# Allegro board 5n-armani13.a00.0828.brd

Outline 226.83 x 115.8 mm; copper layers: TOP, GND1, IN1, VCC, IN2, IN3, GND2, BOTTOM. Coordinates in mm from the lower left corner of the outline.
Outline path: 0,101.3 arc(0.15,101.65) 0.5,101.8 2.2,101.8 arc(2.55,101.65) 2.7,101.3 2.7,101.24 2.7,101.23 arc(2.86,100.89) 3.2,100.75 6.98,100.75 arc(7.69,100.46) 7.98,99.75 7.98,97.48 arc(8.72,95.72) 10.48,95 14.44,95 arc(15.59,95.23) 16.56,95.88 17.1,96.42 arc(18.08,97.07) 19.22,97.3 22.83,97.3 arc(25.65,98.46) 26.83,101.27 26.83,108.59 arc(26.91,108.97) 27.12,109.29 29.54,111.71 arc(29.86,111.92) 30.25,112 79.83,112 arc(80.18,112.14) 80.33,112.48 80.33,112.49 80.33,113 arc(80.48,113.35) 80.83,113.5 91.83,113.5 arc(92.53,113.78) 92.83,114.48 92.83,114.49 92.83,114.8 arc(93.12,115.51) 93.83,115.8 155.38,115.8 arc(156.09,115.51) 156.38,114.8 156.38,112.32 arc(158.88,109.85) 161.38,112.32 161.38,114.8 arc(161.67,115.51) 162.38,115.8 195.84,115.8 arc(196.52,115.53) 196.84,114.88 arc(198.33,113.5) 199.83,114.88 arc(200.15,115.53) 200.82,115.8 209.52,115.8 arc(210.23,115.51) 210.52,114.8 210.52,98.35 arc(210.23,97.64) 209.52,97.35 208.78,97.35 arc(206.63,95.2) 208.78,93.05 210.72,93.05 arc(211.43,92.76) 211.72,92.05 211.72,58.89 arc(211.55,58.32) 211.08,57.96 210.04,57.55 210.02,57.54 arc(208.84,54.74) 211.64,53.56 arc(212.43,53.53) 212.95,52.94 212.96,52.91 arc(216.06,46.06) 220.55,40.03 220.58,39.99 arc(220.77,39.69) 220.83,39.33 220.83,25.22 220.83,25.21 arc(221.13,24.51) 221.83,24.23 225.83,24.23 arc(226.54,23.94) 226.83,23.23 226.83,1 arc(226.54,0.29) 225.83,0 214.07,0 arc(213.36,0.29) 213.07,1 213.07,4.28 213.07,4.44 arc(213.07,4.44) 213.07,4.44 213.07,4.46 arc(210.9,8.59) 206.28,9.13 206.22,9.11 arc(204.48,8.63) 202.68,8.47 152.95,8.47 arc(152.5,8.36) 152.15,8.07 arc(151.79,7.77) 151.35,7.67 112.49,7.67 arc(111.37,7.77) 110.29,8.08 110.29,8.08 arc(109.6,8.28) 108.88,8.35 106.53,8.35 arc(105.13,7.77) 104.53,6.38 104.53,6.36 104.53,3 arc(104.24,2.29) 103.53,2 25.02,2 arc(19.55,3.32) 15.28,6.99 15.27,7 arc(13.85,8.21) 12.03,8.65 4.76,8.65 arc(3.35,9.24) 2.76,10.65 2.76,43.85 5.53,43.85 5.53,43.29 5.53,43.28 arc(5.98,42.85) 6.43,43.28 6.43,43.29 6.43,43.85 11.28,43.85 11.28,43.83 arc(12.14,43.51) 11.78,44.35 11.78,50.45 arc(12.14,51.29) 11.28,50.97 11.28,50.95 8.03,50.95 8.03,51.51 8.03,51.52 arc(7.58,51.95) 7.13,51.52 7.13,51.51 7.13,50.95 1.56,50.95 1.56,51.61 1.56,51.62 arc(1.39,52.16) 0.95,52.52 0.9,52.54 arc(0.47,52.91) 0.31,53.46 0.31,55 arc(0.58,55.69) 1.26,56 arc(1.92,56.3) 2.2,56.98 2.2,56.99 2.2,58.65 9.18,58.65 arc(9.68,59.15) 9.18,59.65 9.18,73.15 arc(9.68,73.65) 9.18,74.15 2.2,74.15 2.2,76.71 2.2,76.73 arc(2.01,77.3) 1.52,77.65 arc(1.02,78.01) 0.83,78.6 0.83,79.7 0.83,79.7 arc(0.03,81.18) 1.33,82.25 1.42,82.25 4.56,82.25 4.56,82.23 arc(5.42,81.91) 5.06,82.75 5.06,91.25 arc(5.42,92.1) 4.56,91.77 4.56,91.75 0,91.75 0,94.64 2.16,94.64 arc(2.84,94.91) 3.15,95.58 3.16,95.6 3.16,95.6 3.16,95.62 arc(2.86,96.32) 2.16,96.6 0,96.6 0,101.3

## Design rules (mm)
net group 45-50OHM(5|4.8|5.5|4.8): nets CSA0_1# CSA1_1#
net group (5/5): nets PROCHOT#_R VR_HOT#_VCPU
net group (15/15): nets I2C0_SCL_TCH_PAD I2C_SCL_TP_MOS
net group (20): nets AUX EDP_COMP
net group (20/20): nets M_CHA_VREF_CA M_CHB_VREF_CA
net group (40): nets RING2 SLEEVE
net group (GND_20): nets AGND GND
net group AU1_CBN: nets AU1_CBN AU1_CBP
net group AUX_ON: nets AUX_ON PU5102_EN2_A
net group AZ_BITCLK_1: nets AZ_BITCLK_1 HDA_BCLK_R
net group AZ_SDATA_IN0: nets AZ_SDATA_IN0 SDATA_IN_R
net group AZ_SDATA_OUT_1: nets AZ_SDATA_OUT_1 HDA_SDO_R
net group AZ_SYNC_1: nets AZ_SYNC_1 HDA_SYNC_R
net group CCG4_I2C_SCL: nets CCG4_I2C_SCL TYPEC_SMBCLK
net group CCG4_I2C_SDA: nets CCG4_I2C_SDA TYPEC_SMBDA
net group CFAN_PWM_R: nets CFAN_PWM_R FAN1_PWM
net group CHG_BGATE_C: nets CHG_BGATE_C CHG_BGATE_R_C
net group CHG_CSON: nets CHG_CSON CHG_CSOP
net group CHG_DCIN_B: nets CHG_DCIN_B CHG_DCIN_R
net group CHG_PROCHOT#: nets CHG_PROCHOT# PROCHOT#
net group CHG_PSYS: nets CHG_PSYS CHG_PSYS_R
net group CHG_SCL_R: nets CHG_SCL_R CHG_SMBCLK
net group CHG_SDA_R: nets CHG_SDA_R CHG_SMBDAT
net group CHG_UG1_D: nets CHG_UG1_D CHG_UG1_R_D
net group CHG_UG2_D: nets CHG_UG2_D CHG_UG2_R_D
net group CLK_PCIE_SSD_REQ#_R: nets CLK_PCIE_NVME_REQ# CLK_PCIE_SSD_REQ#_R
net group CMP_VOUT0: nets CMP_VOUT0 N148505031
net group COMP_B_VCPU: nets COMP_B_VCPU COMP_B_VCPU_R
net group CPU_DP1_HPD: nets CPU_DP1_HPD HDMI_HPD
net group CTAL_1: nets CTAL_1 RTC_X1
net group DC_IN_OK: nets DC_IN_OK HW_ACAVIN_NB
net group DDPC_AUXN: nets DDPC_AUXN OUT1_DP_AUXN_C
net group DDPC_AUXP: nets DDPC_AUXP OUT1_DP_AUXP_C
net group DEVSLP0_HDD: nets DEVSLP0_HDD HDD_DEVSLP
net group DEVSLP2_SSD: nets DEVSLP2_SSD SSD_DEVSLP
net group DMIC_CLK: nets DMIC_CLK DMIC_CLK_R
net group DMIC_DATA: nets DMIC_DATA DMIC_DATA_R
net group DN1: nets DN1 DN1_MUX
net group DN2: nets DN2 DN2_MUX
net group DP1: nets DP1 DP1_MUX
net group DP2: nets DP2 DP2_MUX
net group DP_DDI2_DATA0: nets DP_DDI2_DATA0 OUT1_DP_D0P_C
net group DP_DDI2_DATA0#: nets DP_DDI2_DATA0# OUT1_DP_D0N_C
net group DP_DDI2_DATA1: nets DP_DDI2_DATA1 OUT1_DP_D1P_C
net group DP_DDI2_DATA1#: nets DP_DDI2_DATA1# OUT1_DP_D1N_C
net group DP_DDI2_DATA2: nets DP_DDI2_DATA2 OUT1_DP_D2P_C
net group DP_DDI2_DATA2#: nets DP_DDI2_DATA2# OUT1_DP_D2N_C
net group DP_DDI2_DATA3: nets DP_DDI2_DATA3 OUT1_DP_D3P_C
net group DP_DDI2_DATA3#: nets DP_DDI2_DATA3# OUT1_DP_D3N_C
net group EC_MUTE#: nets EC_MUTE# NB_MUTE#
net group EDP_AUXN: nets EDP_AUXN EDP_AUXN_CC
net group EDP_AUXP: nets EDP_AUXP EDP_AUXP_CC
net group EDP_HPD: nets EDP_HPD EDP_HPD_R
net group EDP_TXN0: nets EDP_TXN0 EDP_TXN0_CC
net group EDP_TXN1: nets EDP_TXN1 EDP_TXN1_CC
net group EDP_TXP0: nets EDP_TXP0 EDP_TXP0_CC
net group EDP_TXP1: nets EDP_TXP1 EDP_TXP1_CC
net group EMMC_CCLK: nets EMMC_CCLK EMMC_CLK_R
net group ESPI_CLK: nets ESPI_CLK PCH_ESPI_CLK
net group ESPI_CS#: nets ESPI_CS# PCH_ESPI_CS#
net group ESPI_IO0: nets ESPI_IO0 PCH_ESPI_IO0
net group ESPI_IO1: nets ESPI_IO1 PCH_ESPI_IO1
net group ESPI_IO2: nets ESPI_IO2 PCH_ESPI_IO2
net group ESPI_IO3: nets ESPI_IO3 PCH_ESPI_IO3
net group FFS_INT1: nets FFS_INT1 INT1
net group GPIO: nets GPU_OVERT GPU_PWR_LEVEL
net group GPU_OVERT_R: nets GPU_OVERT_R N148505032
net group GPU_THM_SMBCLK: nets GPU_THM_SMBCLK SML1_SMBCLK
net group GPU_THM_SMBDAT: nets GPU_THM_SMBDAT SML1_SMBDATA
net group H_CPU_SVIDALERT#: nets VIDALERT# VIDALERT#_VCPU
net group H_CPU_SVIDCLK: nets H_CPU_SVIDCLK VIDSCLK
net group H_PECI: nets H_PECI PECI_PCH
net group HDMI_DDC: nets N153451943 N153451944
net group HPOUT_L: nets HPOUT_L RR_HPOUT_L
net group HPOUT_R: nets HPOUT_R RR_HPOUT_R
net group L_BKLT_CTRL: nets L_BKLT_CTRL L_BKLT_CTRL_R
net group LANWAKE#: nets LAN_WAKE# LANWAKE#
net group M_CH_DRAM_RESET#: nets M_CH_DRAM_RESET# M_CH_DRAM_RESET#_R
net group M_OTHER: nets N16941314 N144273293
net group ME_SUS_PWR_ACK: nets ME_SUS_PWR_ACK SUSACK#
net group N147968560: nets N147968560 N147968575
net group PANEL_BKEN_EC: nets PANEL_BKEN_EC PANEL_BKEN_EC_R
net group PBAT_PRES#: nets N154222504 PBAT_PRES#
net group PCIE1_GPU_RXN: nets PCIE1_GPU_RXN PCIE1_GPU_RXN_C
net group PCIE1_GPU_RXP: nets PCIE1_GPU_RXP PCIE1_GPU_RXP_C
net group PCIE1_GPU_TXN: nets PCIE1_GPU_TXN PCIE1_GPU_TXN_C
net group PCIE1_GPU_TXP: nets PCIE1_GPU_TXP PCIE1_GPU_TXP_C
net group PCIE2_GPU_RXN: nets PCIE2_GPU_RXN PCIE2_GPU_RXN_C
net group PCIE2_GPU_RXP: nets PCIE2_GPU_RXP PCIE2_GPU_RXP_C
net group PCIE2_GPU_TXN: nets PCIE2_GPU_TXN PCIE2_GPU_TXN_C
net group PCIE2_GPU_TXP: nets PCIE2_GPU_TXP PCIE2_GPU_TXP_C
net group PCIE3_GPU_RXN: nets PCIE3_GPU_RXN PCIE3_GPU_RXN_C
net group PCIE3_GPU_RXP: nets PCIE3_GPU_RXP PCIE3_GPU_RXP_C
net group PCIE3_GPU_TXN: nets PCIE3_GPU_TXN PCIE3_GPU_TXN_C
net group PCIE3_GPU_TXP: nets PCIE3_GPU_TXP PCIE3_GPU_TXP_C
net group PCIE4_GPU_RXN: nets PCIE4_GPU_RXN PCIE4_GPU_RXN_C
net group PCIE4_GPU_RXP: nets PCIE4_GPU_RXP PCIE4_GPU_RXP_C
net group PCIE4_GPU_TXN: nets PCIE4_GPU_TXN PCIE4_GPU_TXN_C
net group PCIE4_GPU_TXP: nets PCIE4_GPU_TXP PCIE4_GPU_TXP_C
net group PCIE5_LAN_TXN: nets PCIE5_LAN_TXN PCIE5_LAN_TXN_C
net group PCIE5_LAN_TXP: nets PCIE5_LAN_TXP PCIE5_LAN_TXP_C
net group PCIE6_WLAN_TXN: nets PCIE6_WLAN_TXN PCIE6_WLAN_TXN_C
net group PCIE6_WLAN_TXP: nets PCIE6_WLAN_TXP PCIE6_WLAN_TXP_C
net group PCIE9_SSD1_TXN: nets PCIE9_SSD1_TXN PCIE9_SSD1_TXN_C
net group PCIE9_SSD1_TXP: nets PCIE9_SSD1_TXP PCIE9_SSD1_TXP_C
net group PCIE10_SSD1_TXN: nets PCIE10_SSD1_TXN PCIE10_SSD1_TXN_C
net group PCIE10_SSD1_TXP: nets PCIE10_SSD1_TXP PCIE10_SSD1_TXP_C
net group PCIE11_SSD1_TXN: nets PCIE11_SSD1_TXN PCIE11_SSD1_TXN_C
net group PCIE11_SSD1_TXP: nets PCIE11_SSD1_TXP PCIE11_SSD1_TXP_C
net group PCIE12_SATA_SSD1_RXN: nets PCIE12_SATA_SSD1_RXN PCIE12_SATA_SSD1_RXN_R
net group PCIE12_SATA_SSD1_RXP: nets PCIE12_SATA_SSD1_RXP PCIE12_SATA_SSD1_RXP_R
net group PCIE12_SATA_SSD1_TXN: nets PCIE12_SATA_SSD1_TXN PCIE12_SATA_SSD1_TXN_C
net group PCIE12_SATA_SSD1_TXP: nets PCIE12_SATA_SSD1_TXP PCIE12_SATA_SSD1_TXP_C
net group PD_HPD: nets PD_HPD PD_HPD_R
net group PGOOD_VCPU: nets PGOOD_VCPU VRM_PWRGD
net group PU5104_EN2_A: nets PU5104_EN2_A VCCDSW_EN
net group RTC: nets RTC_RST# SRTC_RST#
net group RX1N_P1: nets RX1N_P1 RX1N_P1_MUX
net group RX1P_P1: nets RX1P_P1 RX1P_P1_MUX
net group RX2N_P1: nets RX2N_P1 RX2N_P1_MUX
net group RX2P_P1: nets RX2P_P1 RX2P_P1_MUX
net group SCS#_TPM: nets SCS#_TPM SPI_CS2#
net group SPI_SI: nets SPI_SI SPI_SI_R
net group SPI_SO: nets SPI_SO SPI_SO_R
net group SPK_L+: nets SPK_L+ SPK_L+_R
net group SPK_L-: nets SPK_L- SPK_L-_R
net group SPK_R+: nets SPK_R+ SPK_R+_R
net group SPK_R-: nets SPK_R- SPK_R-_R
net group SYS_PWROK: nets SYS_PWROK SYS_PWROK_R
net group USB3_RX_N3: nets USB3_RX_N3 USB3_RX_N3_C
net group USB3_RX_P3: nets USB3_RX_P3 USB3_RX_P3_C
net group USB3_TX_N3: nets USB3_TX_N3 USB3_TX_N3_C
net group USB3_TX_P3: nets USB3_TX_P3 USB3_TX_P3_C
net group USBP5+_CAM: nets USBP5+_CAM USBP5_CAM
net group USBP5-_CAM: nets USBN5_CAM USBP5-_CAM
net group XTAL_24M_IN: nets XTAL_24M_IN XTAL_24M_IN_R
net group XTAL_24M_IN_R_U42: nets XTAL_24M_IN_R_U42 XTAL_24M_IN_U42
net group XTAL_24M_OUT: nets XTAL_24M_OUT XTAL_24M_OUT_R
net group XTAL_24M_OUT_R_U42: nets XTAL_24M_OUT_R_U42 XTAL_24M_OUT_U42
net group XTALIN: nets XTALIN XTALIN_GR
net group 3P3VSB_EN2: nets 3P3VSB_EN2 5VSB_EN1 N148388543
net group 40OHM(6.5|6|6|6): nets DDR0_A_ALERT_N DDR0_A_PARITY DDR1_B_ALERT_N DDR1_B_PARITY M_A_A0 M_A_A1 M_A_A2 M_A_A3 M_A_A4 M_A_A5 M_A_A6 M_A_A7 M_A_A8 M_A_A9 M_A_A10 M_A_A11 M_A_A12 M_A_A13 M_A_A14 M_A_A15 M_A_A16 M_A_ACT_N M_A_BA0 M_A_BA1 M_A_BG0 M_A_BG1 M_A_DIM0_CKE0 M_A_DIM0_CKE1 M_A_DIM0_CS#0 M_A_DIM0_CS#1 M_A_DIM0_ODT0 M_A_DIM0_ODT1 M_B_A0 M_B_A1 M_B_A2 M_B_A3 M_B_A4 M_B_A5 M_B_A6 M_B_A7 M_B_A8 M_B_A9 M_B_A10 M_B_A11 M_B_A12 M_B_A13 M_B_A14 M_B_A15 M_B_A16 M_B_ACT_N M_B_BA0 M_B_BA1 M_B_BG0 M_B_BG1 M_B_DIM0_CKE0 M_B_DIM0_CKE1 M_B_DIM0_CS#0 M_B_DIM0_CS#1 M_B_DIM0_ODT0 M_B_DIM0_ODT1
net group 50OHM(4|3.8|4.3|5): nets CCG4_I2C_SCL_MUX CCG4_I2C_SDA_MUX CLK_PCIE_PEG_REQ# CLK_PCIE_WLAN_REQ# CLK_TP_SIO CLK_TP_SIO_C CPU_DP1_CTRL_CLK CPU_DP1_CTRL_DATA DAT_TP_SIO DAT_TP_SIO_C EMMC_CMD EMMC_RCLK HDA_RST#_R HDA_SDI1_DSP HDMI_SCLK_SNK HDMI_SDATA_SNK ME_FWP MEM_SMBCLK MEM_SMBCLK_D MEM_SMBDATA MEM_SMBDATA_D MISO_TPM MOSI_TPM N152371714 PBAT_SMBCLK PBAT_SMBDAT SMB_ALERT# SMB_THERMAL_CLK SMB_THERMAL_DATA SML0_ALERT# SML0_SMBCLK SML0_SMBDATA SML1ALERT# SPI_CS0# SPI_CS1# SPI_HOLD#_IO3 SPI_WP_IO2 USB2_COMP XCLK_BIASREF XTALOUT
net group 50OHM_REF(4|3.8|3.8|3.8): nets M_A_D0 M_A_D1 M_A_D2 M_A_D3 M_A_D4 M_A_D5 M_A_D6 M_A_D7 M_A_D8 M_A_D9 M_A_D10 M_A_D11 M_A_D12 M_A_D13 M_A_D14 M_A_D15 M_A_D16 M_A_D17 M_A_D18 M_A_D19 M_A_D20 M_A_D21 M_A_D22 M_A_D23 M_A_D24 M_A_D25 M_A_D26 M_A_D27 M_A_D28 M_A_D29 M_A_D30 M_A_D31 M_A_D32 M_A_D33 M_A_D34 M_A_D35 M_A_D36 M_A_D37 M_A_D38 M_A_D39 M_A_D40 M_A_D41 M_A_D42 M_A_D43 M_A_D44 M_A_D45 M_A_D46 M_A_D47 M_A_D48 M_A_D49 M_A_D50 M_A_D51 M_A_D52 M_A_D53 M_A_D54 M_A_D55 M_A_D56 M_A_D57 M_A_D58 M_A_D59 M_A_D60 M_A_D61 M_A_D62 M_A_D63 M_B_D0 M_B_D1 M_B_D2 M_B_D3 M_B_D4 M_B_D5 M_B_D6 M_B_D7 M_B_D8 M_B_D9 M_B_D10 M_B_D11 M_B_D12 M_B_D13 M_B_D14 M_B_D15 M_B_D16 M_B_D17 M_B_D18 M_B_D19 M_B_D20 M_B_D21 M_B_D22 M_B_D23 M_B_D24 M_B_D25 M_B_D26 M_B_D27 M_B_D28 M_B_D29 M_B_D30 M_B_D31 M_B_D32 M_B_D33 M_B_D34 M_B_D35 M_B_D36 M_B_D37 M_B_D38 M_B_D39 M_B_D40 M_B_D41 M_B_D42 M_B_D43 M_B_D44 M_B_D45 M_B_D46 M_B_D47 M_B_D48 M_B_D49 M_B_D50 M_B_D51 M_B_D52 M_B_D53 M_B_D54 M_B_D55 M_B_D56 M_B_D57 M_B_D58 M_B_D59 M_B_D60 M_B_D61 M_B_D62 M_B_D63
net group 83OHM(DP_4.3|4.8|6|5.3/4|4.5|4|4/5/200): nets M_A_DQS0 M_A_DQS1 M_A_DQS2 M_A_DQS3 M_A_DQS4 M_A_DQS5 M_A_DQS6 M_A_DQS7 M_A_DQS#0 M_A_DQS#1 M_A_DQS#2 M_A_DQS#3 M_A_DQS#4 M_A_DQS#5 M_A_DQS#6 M_A_DQS#7 M_B_DQS0 M_B_DQS1 M_B_DQS2 M_B_DQS3 M_B_DQS4 M_B_DQS5 M_B_DQS6 M_B_DQS7 M_B_DQS#0 M_B_DQS#1 M_B_DQS#2 M_B_DQS#3 M_B_DQS#4 M_B_DQS#5 M_B_DQS#6 M_B_DQS#7
net group 85OHM(DP_4|4.3|4|5/4/5/200): nets CLKPCIE_GPU_N0 CLKPCIE_GPU_P0 CLKPCIE_SSD_N4 CLKPCIE_SSD_P4 PCIE9_SSD1_RXN PCIE9_SSD1_RXP PCIE10_SSD1_RXN PCIE10_SSD1_RXP PCIE11_SSD1_RXN PCIE11_SSD1_RXP USBN1 USBN3_TYPEC USBN4 USBN6_SD USBP1 USBP3_TYPEC USBP4 USBP6_SD
net group 85OHM_REF(DP_4|4.3|4.3|4.3/4/5/200): nets M_A_DIM0_CLK0 M_A_DIM0_CLK1 M_A_DIM0_CLK#0 M_A_DIM0_CLK#1 M_B_DIM0_CLK0 M_B_DIM0_CLK1 M_B_DIM0_CLK#0 M_B_DIM0_CLK#1
net group (10): nets AU1_LD3_CAP PC_BEEP PCBEEP PCBEEP_R
net group (10/10): nets AU1_HPOUT1_JD# EMMC_DATA0 EMMC_DATA1 EMMC_DATA2 EMMC_DATA3 EMMC_DATA4 EMMC_DATA5 EMMC_DATA6 EMMC_DATA7 H_CPU_SVIDALERT# HPOUT1_JD# VIDSCLK_VCPU
net group (12/12): nets THRMTRIP# VCCST_PWRGD VCCST_PWRGD_R
net group (15): nets PCIE_RCOMPN PCIE_RCOMPP R_HPOUT_L R_HPOUT_R
net group (PWR_20): nets +0.95V_GPU_DISCH_A +0P95VGA_EN +1.0VO +1.8VALW_EC +1.8VO_VGA_PWRGD +1.8VS_VGA_DISCH_A +1P2V_DUAL +1P2V_DUAL_A_CS +1P2V_DUAL_A_FB_A +1P2V_DUAL_A_S3 +1P2V_DUAL_A_TON +1P2V_DUAL_A_V5IN +1P2V_DUAL_A_VOUT_R_A +1P2V_DUAL_BST +1P2V_DUAL_BST_RC +1P2V_DUAL_SUR +1P2V_DUAL_VIN +1P8V +1P8V_CPVDD +1P8V_EMMC +1P8VSB +1P8VSB_COMP_A +1P8VSB_EN_A +1P8VSB_FB1_A +1P8VSB_FB_A +1P8VSB_OUT +1P8VSB_SW +1P8VSB_VIN +1P8VSUS_ORG +1VSB +1VSB_VIN +1VSUS_ORG +2P5_VPP_COMP_A +2P5_VPP_FB1_A +2P5_VPP_FB_A +2P5_VPP_SW +2P5_VPP_VIN +2P5V_VPP +2P5V_VPP_EN_A +2P5V_VPP_PWRGD +3P3V +3P3V_CAM +3P3V_CCG4 +3P3V_DONGLE +3P3V_DVDD +3P3V_EMMC +3P3V_LAN +3P3V_PAD +3P3V_PANEL +3P3V_PANEL_O +3P3V_SENSOR +3P3V_SSD +3P3V_TPM +3P3V_TUSB546 +3P3VA +3P3VA_CS2_A +3P3VSB +3P3VSB_BST1_C +3P3VSB_BST_C +3P3VSB_FB_A +3P3VSB_FBR_A +3P3VSB_SN_S +3P3VSB_TPM +3V_CCG4_TYPEC +3V_CCG4_VDDD +3VALW_EC +3VSUS_ORG +5V +5V_3V_VCLK +5V_3V_VIN +5V_ANALOG +5V_CCG4 +5V_HDD +5V_HDMI +5V_KB +5V_PVDD +5VA +5VSB +5VSB&+3P3VSB_IN +5VSB_BST1_C +5VSB_BST_C +5VSB_CS1_A +5VSB_FB_A +5VSB_FBR_A +5VSB_SN_S +5VSB_VO +19VADC_VIN +AC_BAT_SYS +BL_PWR +BL_PWR_O +CPU_VIN1_A +DCIN_IN +FBVDDQ +FBVDDQ_DISCH_A +RTC_CELL_VBAT +USB_TYPEC +VBATT +VBATT_F +VCC_RTC +VCCGT +VCCGT_BT_D +VCCGT_CSN_A +VCCGT_CSP_A +VCCGT_FCCM +VCCGT_PWM +VCCGT_R_BT_D +VCCGT_SN_C +VCCIO +VCCPGPP +VCCPLL_OC +VCCPRIM_CORE +VCCSA +VCCSA_BT_D +VCCSA_CSN_A +VCCSA_CSP_A +VCCSA_FCCM +VCCSA_PWM +VCCSA_R_BT_D +VCCST +VCCSTG +VCORE +VCORE1_BT_D +VCORE1_FCCM +VCORE1_PWM +VCORE1_R_BT_D +VCORE2_FCCM +VCORE2_PWM +VCORE2_R_BT_D +VCORE2_SN_C +VCORE/GT +VCORE_CSN1_A +VCORE_CSP1_A +VCORE_ISEN1_A +VCORE_ISEN2_A +VCORE_SN_C +VDC_IN +VDD +VDDC_VGA_DISCH_A +VDDP +VRTC_BATT +VSUS_ROM +VTT_A_DDR_VTTSNS +VTT_A_REF +VTT_DDR SM_RCOMP_0 SM_RCOMP_1 SM_RCOMP_2
net group +1P8VSB_PWRGD: nets +1P8VSB_PWRGD +1VSB_PWRGD N153332052
net group +VDDQ_PWRGD: nets +VDDQ_PWRGD N153331695 RUNPWROK
net group ACAV_IN_ERP: nets ACAV_IN_ERP ACAV_IN_R ALL_SUS_PWRGD CHG_ACOK CHG_ACOK_R HW_ACAV_IN SUS_PWRGD
net group ALL_SYS_PWRGD: nets ALL_SYS_PWRGD ALL_SYS_PWRGD_R ALL_SYS_PWRGD_VR
net group ASY: nets TP_CATERR#_R
net group AUDIO: nets LINE2_L LINE2_R MIC2_L MIC2_R
net group BB_AMON_BMON: nets BB_AMON_BMON CHG_AMON_R I_ADP I_BATT
net group CHG_BOOT1_D: nets CHG_BOOT1_D CHG_BOOT2_D CHG_PH1_D CHG_PH2_D
net group CHG_CSIN: nets CHG_CSIN CHG_CSIP CSIN_R CSIP_R
net group FFS_INT2: nets FFS_INT2 FFS_INT2_HDD INT2
net group H_CPU_SVIDDAT: nets H_CPU_SVIDDAT VIDSOUT VIDSOUT_VCPU
net group HDMI_CLKN_SNK: nets HDMI_CLKN_SNK HDMI_DATA3# HDMI_TMDS_CLK_N
net group HDMI_CLKP_SNK: nets HDMI_CLKP_SNK HDMI_DATA3 HDMI_TMDS_CLK_P
net group HDMI_DATA0: nets HDMI_DATA0 HDMI_TMDS_DATA2_P HDMI_TXP2_SNK
net group HDMI_DATA0#: nets HDMI_DATA0# HDMI_TMDS_DATA2_N HDMI_TXN2_SNK
net group HDMI_DATA1: nets HDMI_DATA1 HDMI_TMDS_DATA1_P HDMI_TXP1_SNK
net group HDMI_DATA1#: nets HDMI_DATA1# HDMI_TMDS_DATA1_N HDMI_TXN1_SNK
net group HDMI_DATA2: nets HDMI_DATA2 HDMI_TMDS_DATA0_P HDMI_TXP0_SNK
net group HDMI_DATA2#: nets HDMI_DATA2# HDMI_TMDS_DATA0_N HDMI_TXN0_SNK
net group I2C(5/5): nets CCG4_I2C_INT# I2C0_SDA_TCH_PAD I2C_SDA_TP_MOS
net group LGHG(20/20): nets +1P2V_DUAL_HG +1P2V_DUAL_LG +1P2V_DUAL_PHASE +3P3VSB_HG_D +3P3VSB_HGR_D +3P3VSB_LG_D +3P3VSB_LGR_D +3P3VSB_PHASE2_S +5VSB_HG_D +5VSB_HGR_D +5VSB_LG_D +5VSB_LGR_D +5VSB_PHASE1_S +VCCGT_HG_D +VCCGT_LG_D +VCCGT_PHASE_D +VCCGT_R_HG_D +VCCGT_R_LG_D +VCCSA_HG_D +VCCSA_LG_D +VCCSA_PHASE_D +VCCSA_R_HG_D +VCCSA_R_LG_D +VCORE1_HG_D +VCORE1_LG_D +VCORE1_PHASE_D +VCORE1_R_HG_D +VCORE1_R_LG_D +VCORE2_BT_D +VCORE2_HG_D +VCORE2_LG_D +VCORE2_PHASE_D +VCORE2_R_HG_D +VCORE2_R_LG_D CHG_LG1_D CHG_LG2_D N144773302 N144773400
net group M2_SSD_PEDET: nets M2_SSD_PEDET M2_SSD_PEDET_N SSD1_PEDET_R
net group MEC_XTAL2: nets MEC_XTAL2 MEC_XTAL2_R SUSCLK
net group PCH_DPWROK_R: nets PCH_DPWROK_R PCH_RSMRST# PCH_RSMRST#_EC RSMRST#
net group PCH_PLTRST#: nets N17285432 PCH_PLTRST# PLT_RST#_BUF TPM_RST#
net group PM_PCH_PWROK: nets N146967179 PM_PCH_PWROK RESET_OUT#
net group PU5101_EN1: nets PU5101_EN1 PU5101_EN1_A PU5106_EN1_A
net group PU5102_EN1_A: nets PU5102_EN1_A PU5104_EN1_A SIO_SLP_S3#
net group PU5106_EN2_A: nets N152920502 N152921519 PU5106_EN2_A SIO_SLP_S4#
net group RTC(15/15): nets RTC_X2
net group SATA(12/12): nets SATA0_RXN_HDD SATA0_RXN_HDD_C SATA0_RXP_HDD SATA0_RXP_HDD_C SATA0_TXN_HDD SATA0_TXN_HDD_C SATA0_TXP_HDD SATA0_TXP_HDD_C
net group SPI(5/5): nets ESPI_ALERT#
net group SPI_CLK: nets SPI_CLK SPI_CLK_R TPM_SPI_CLK
net group TX1N_P1: nets TX1N_P1 TX1N_P1_C TX1N_P1_MUX
net group TX1P_P1: nets TX1P_P1 TX1P_P1_C TX1P_P1_MUX
net group TX2N_P1: nets TX2N_P1 TX2N_P1_C TX2N_P1_MUX
net group TX2P_P1: nets TX2P_P1 TX2P_P1_C TX2P_P1_MUX

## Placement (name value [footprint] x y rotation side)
C0400  0.01UF/16V  [TX_C0402]  133.78 75.52 180 bottom
C0500  0.1UF/16V  [TX_C0402]  94.65 109.02 180 bottom
C0600  22UF/6.3V  [TX_C0603_T02_H39]  105.92 51.89 0 top
C0601  22UF/6.3V  [TX_C0603_T02_H39]  105.89 58.91 0 top
C0602  22UF/6.3V  [TX_C0603_T02_H39]  107.44 49.58 0 top
C0603  10UF/6.3V  [TX_C0402_T02_H28]  107.93 46.79 0 top
C0604  10UF/6.3V  [TX_C0402_T02_H28]  105.26 48.57 90 top
C0605  10UF/6.3V  [TX_C0402_T02_H28]  105.26 50.19 270 top
C0606  10UF/6.3V  [TX_C0402_T02_H28]  105.23 54.76 270 top
C0607  1UF/6.3V  [TX_C0402]  133.99 24.05 270 bottom
C0608  1UF/6.3V  [TX_C0402]  133.05 24.05 270 bottom
C0609  1UF/6.3V  [TX_C0402]  111.46 49 270 top
C0610  1UF/6.3V  [TX_C0402]  111.56 50.27 180 top
C0611  1UF/6.3V  [TX_C0402]  122.71 47.66 0 top
C0612  10UF/6.3V  [TX_C0402_T02_H28]  109.75 57.05 0 top
C0613  1UF/6.3V  [TX_C0402]  113.72 47.22 90 top
C0614  1UF/6.3V  [TX_C0402]  117.01 47.27 90 top
C0615  1UF/6.3V  [TX_C0402]  114.66 47.22 90 top
C0616  1UF/6.3V  [TX_C0402]  115.59 47.22 90 top
C0617  1UF/6.3V  [TX_C0402]  122.7 48.63 0 top
C0618  1UF/6.3V  [TX_C0402]  117.95 47.26 90 top
C0619  1UF/6.3V  [TX_C0402]  128.55 44.15 90 top
C0620  1UF/6.3V  [TX_C0402]  126.72 45.49 180 top
C0621  1UF/6.3V  [TX_C0402]  111.84 47.43 180 top
C0622  1UF/6.3V  [TX_C0402]  123.04 46.03 90 top
C0623  0.1UF/16V  [TX_C0402]  122.1 46.03 90 top
C0700  1UF/6.3V  [TX_C0402]  111.4 51.37 180 top
C0701  1UF/6.3V  [TX_C0402]  111.4 52.31 180 top
C0702  1UF/6.3V  [TX_C0402]  111.4 53.25 180 top
C0703  1UF/6.3V  [TX_C0402]  113.77 52.56 90 top
C0704  1UF/6.3V  [TX_C0402]  128.68 54.41 90 top
C0705  1UF/6.3V  [TX_C0402]  124.24 53.67 270 top
C0706  1UF/6.3V  [TX_C0402]  126.87 51.62 180 top
C0707  1UF/6.3V  [TX_C0402]  132.56 49.56 270 bottom
C0708  1UF/6.3V  [TX_C0402]  137.74 61.71 180 bottom
C0709  1UF/6.3V  [TX_C0402]  137.74 58.93 180 bottom
C0710  1UF/6.3V  [TX_C0402]  130.92 49.57 270 bottom
C0711  1UF/6.3V  [TX_C0402]  128.65 60.2 270 top
C0712  1UF/6.3V  [TX_C0402]  120.24 54.03 270 top
C0713  1UF/6.3V  [TX_C0402]  137.34 56.67 270 bottom
C0714  1UF/6.3V  [TX_C0402]  137.49 47.88 180 bottom
C0715  1UF/6.3V  [TX_C0402]  137.74 60.78 180 bottom
C0716  1UF/6.3V  [TX_C0402]  137.49 46.94 180 bottom
C0717  1UF/6.3V  [TX_C0402]  124.23 55.48 270 top
C0718  1UF/6.3V  [TX_C0402]  122.85 53.67 270 top
C0719  1UF/6.3V  [TX_C0402]  127.74 54.14 270 top
C0720  1UF/6.3V  [TX_C0402]  113.97 65.43 270 top
C0721  1UF/6.3V  [TX_C0402]  120.75 65.43 270 top
C0722  1UF/6.3V  [TX_C0402]  122.6 64.85 0 top
C0723  1UF/6.3V  [TX_C0402]  120.75 63.81 90 top
C0724  1UF/6.3V  [TX_C0402]  119.43 65.43 270 top
C0725  1UF/6.3V  [TX_C0402]  122.6 61.02 0 top
C0726  1UF/6.3V  [TX_C0402]  122.61 61.95 0 top
C0727  1UF/6.3V  [TX_C0402]  122.6 62.97 0 top
C0728  1UF/6.3V  [TX_C0402]  122.6 63.91 0 top
C0729  1UF/6.3V  [TX_C0402]  116.69 65.43 270 top
C0730  1UF/6.3V  [TX_C0402]  118.08 65.43 270 top
C0731  1UF/6.3V  [TX_C0402]  119.51 76.33 0 top
C0732  1UF/6.3V  [TX_C0402]  121.13 76.33 180 top
C0733  1UF/6.3V  [TX_C0402]  115.29 65.43 270 top
C0734  1UF/6.3V  [TX_C0402]  137.74 58.02 180 bottom
C0735  1UF/6.3V  [TX_C0402]  137.74 59.84 180 bottom
C0736  1UF/6.3V  [TX_C0402]  137.49 48.82 180 bottom
C0737  1UF/6.3V  [TX_C0402]  136.2 49.48 270 bottom
C0738  1UF/6.3V  [TX_C0402]  135.23 49.47 270 bottom
C0739  1UF/6.3V  [TX_C0402]  133.5 49.56 270 bottom
C0740  1UF/6.3V  [TX_C0402]  111.41 55.11 180 top
C0741  1UF/6.3V  [TX_C0402]  113.82 54.61 270 top
C0742  1UF/6.3V  [TX_C0402]  122.83 55.46 270 top
C0743  1UF/6.3V  [TX_C0402]  122.86 52 270 top
C0744  1UF/6.3V  [TX_C0402]  111.41 54.18 180 top
C0745  1UF/6.3V  [TX_C0402]  122.57 60.01 0 top
C0746  1UF/6.3V  [TX_C0402]  122.57 59.08 0 top
C0747  1UF/6.3V  [TX_C0402]  126.81 60.82 180 top
C0748  1UF/6.3V  [TX_C0402]  111.63 59.76 180 top
C0749  1UF/6.3V  [TX_C0402]  111.63 58.82 180 top
C0900  10PF/50V  [TX_C0402]  126.97 27.21 0 bottom
C0901  10PF/50V  [TX_C0402]  130.2 27.36 180 bottom
C1000  10PF/50V  [TX_C0402]  132.54 51.29 90 bottom
C1001  10PF/50V  [TX_C0402]  132.54 54.54 270 bottom
C1002  10PF/50V  [TX_C0402]  92.94 44.14 270 top
C1003  10PF/50V  [TX_C0402]  93.6 42.24 270 top
C1004  10PF/50V  [TX_C0402]  97.03 44.25 90 bottom
C1005  1UF/6.3V  [TX_C0402]  110.72 21.87 180 bottom
C1006  1UF/6.3V  [TX_C0402]  108.64 22.28 270 bottom
C1100  27PF/50V  [TX_C0402]  91.57 35.38 270 top
C1101  27PF/50V  [TX_C0402]  92.61 35.38 270 top
C1102  27PF/50V  [TX_C0402]  93.55 35.38 270 top
C1103  27PF/50V  [TX_C0402]  94.46 35.38 270 top
C1104  27PF/50V  [TX_C0402]  100.66 30.43 270 bottom
C1105  27PF/50V  [TX_C0402]  98.78 30.43 270 bottom
C1200  0.1UF/16V  [TX_C0402]  101.09 26.93 0 bottom
C1201  0.1UF/16V  [TX_C0402]  65.58 10.92 270 top
C1202  0.1UF/16V  [TX_C0402]  66.57 10.92 270 top
C1203  0.1UF/16V  [TX_C0402]  99.49 41.28 180 bottom
C1204  0.1UF/16V  [TX_C0402]  91.54 30.41 270 top
C1205  0.1UF/16V  [TX_C0402]  91.62 26.75 270 top
C1206  0.1UF/16V  [TX_C0402]  98.07 16.11 180 bottom
C1207  0.1UF/16V  [TX_C0402]  97.51 25.89 180 bottom
C1600  1UF/6.3V  [TX_C0402]  115.77 44.45 90 top
C1601  1UF/6.3V  [TX_C0402]  115.77 42.83 90 top
C1602  1UF/6.3V  [TX_C0402]  118.76 29.95 180 top
C1603  1UF/6.3V  [TX_C0402]  118.76 29.01 180 top
C1604  1UF/6.3V  [TX_C0402]  116.85 25.28 270 bottom
C1605  1UF/6.3V  [TX_C0402]  117.15 44.49 90 top
C1606  1UF/6.3V  [TX_C0402]  120.96 42.43 180 top
C1607  47uF/6.3V  [TX_C0603_T02_H39]  131.7 27.36 270 bottom
C1608  1UF/6.3V  [TX_C0402]  121.72 30.55 0 top
C1609  47uF/6.3V  [TX_C0603_T02_H39]  134.57 29.61 180 bottom
C1610  1UF/6.3V  [TX_C0402]  130.99 30.11 270 bottom
C1611  1UF/6.3V  [TX_C0402]  110.58 31.43 90 top
C1612  1UF/6.3V  [TX_C0402]  116.81 30.86 0 top
C1613  1UF/6.3V  [TX_C0402]  122 29.63 0 top
C1614  0.1UF/16V  [TX_C0402]  118.26 44.99 90 top
C1615  2.2UF/6.3V  [TX_C0402]  117.93 42.31 180 top
C1616  47uF/6.3V  [TX_C0603_T02_H39]  132.68 32.36 180 bottom
C1617  0.1UF/16V  [TX_C0402]  99.72 30.43 270 bottom
C1618  0.1UF/16V  [TX_C0402]  96.55 32.54 180 top
C1619  1UF/6.3V  [TX_C0402]  114.73 44.81 270 top
C1620  1UF/6.3V  [TX_C0402]  113.79 44.27 90 top
C1621  47uF/6.3V  [TX_C0603_T02_H39]  124.53 43.05 90 top
C1622  1UF/6.3V  [TX_C0402]  118.03 43.23 180 top
C1623  47uF/6.3V  [TX_C0603_T02_H39]  124.47 45.92 90 top
C1624  47uF/6.3V  [TX_C0603_T02_H39]  125.88 43.91 270 top
C1625  1UF/6.3V  [TX_C0402]  119.57 44.1 90 top
C1626  1UF/6.3V  [TX_C0402]  120.52 44.83 270 top
C1627  47uF/6.3V  [TX_C0603_T02_H39]  138.3 31.4 0 bottom
C1628  47uF/6.3V  [TX_C0603_T02_H39]  113 19.87 0 bottom
C1629  0.1UF/16V  [TX_C0402]  118.85 28.07 0 top
C1630  68PF/50V  [TX_C0402]  119.35 21.24 90 top
C1631  1000PF/25V  [TX_C0402]  115.7 23.9 0 bottom
C1632  2200PF/50V  [TX_C0402]  133.4 22.18 90 top
C1633  47uF/6.3V  [TX_C0603_T02_H39]  114.1 25.66 180 bottom
C1634  47uF/6.3V  [TX_C0603_T02_H39]  121.23 28.32 270 bottom
C1800  0.1UF/16V  [TX_C0402]  12.9 17.3 0 top
C1900  0.1UF/16V  [TX_C0402]  104.65 17.99 270 bottom
C1901  10PF/50V  [TX_C0402]  18.29 49.18 90 bottom
C1902  10PF/50V  [TX_C0402]  19.79 43.39 270 bottom
C1903  10PF/50V  [TX_C0402]  39.93 84.41 90 top
C1904  10PF/50V  [TX_C0402]  29.29 55.5 90 top
C1905  10PF/50V  [TX_C0402]  73.81 17.17 90 top
C1906  10PF/50V  [TX_C0402]  74.3 22.66 90 top
C2000  10PF/50V  [TX_C0402]  62.13 27.16 180 top
C2001  10PF/50V  [TX_C0402]  70.08 26.01 0 top
C2002  0.1UF/16V  [TX_C0402]  62.13 65.71 0 top
C2003  2.2UF/6.3V  [TX_C0402]  108.28 26.49 0 top
C2004  10PF/50V  [TX_C0402]  108.28 25.56 0 top
C2005  10PF/50V  [TX_C0402]  70.13 28.17 0 top
C2006  100PF/50V  [TX_C0402]  62.13 28.22 180 top
C2007  0.1UF/16V  [TX_C0402]  59.39 50.18 180 top
C2008  0.022UF/16V  [TX_C0402]  59.39 49.24 180 top
C2009  0.1UF/16V  [TX_C0402]  61.54 50.51 180 top
C2010  2.2UF/6.3V  [TX_C0402]  61.54 47.67 180 top
C2011  0.1UF/16V  [TX_C0402]  62.1 64.77 0 top
C2012  0.1UF/16V  [TX_C0402]  70.08 26.93 0 top
C2100  10PF/50V  [TX_C0402]  47.12 25.11 270 top
C2101  10PF/50V  [TX_C0402]  57.58 27.26 0 top
C2102  0.1UF/16V  [TX_C0402]  45.9 62.66 90 top
C2103  2.2UF/6.3V  [TX_C0402]  57.58 29.34 0 top
C2104  0.1UF/16V  [TX_C0402]  51.77 25 0 top
C2105  10PF/50V  [TX_C0402]  57.58 30.38 0 top
C2106  10PF/50V  [TX_C0402]  57.58 28.3 0 top
C2107  100PF/50V  [TX_C0402]  52.63 26.9 180 top
C2108  0.1UF/16V  [TX_C0402]  47.56 50.54 180 top
C2109  0.022UF/16V  [TX_C0402]  47.56 51.53 180 top
C2110  0.1UF/16V  [TX_C0402]  49.6 46.98 180 top
C2111  2.2UF/6.3V  [TX_C0402]  49.6 47.92 180 top
C2200  10UF/6.3V  [TX_C0402_T02_H28]  62.41 77.88 0 top
C2201  10UF/6.3V  [TX_C0402_T02_H28]  69.21 62.71 90 top
C2202  10UF/6.3V  [TX_C0402_T02_H28]  64.24 52.96 0 top
C2203  10UF/6.3V  [TX_C0402_T02_H28]  68.28 31.27 180 top
C2204  10UF/6.3V  [TX_C0402_T02_H28]  69.68 46.35 180 top
C2205  10UF/6.3V  [TX_C0402_T02_H28]  69.42 51.16 180 top
C2206  10UF/6.3V  [TX_C0402_T02_H28]  62.4 69.83 0 top
C2207  10UF/6.3V  [TX_C0402_T02_H28]  70.28 60.81 180 top
C2208  10UF/6.3V  [TX_C0402_T02_H28]  44.29 25.11 270 top
C2209  10UF/6.3V  [TX_C0402_T02_H28]  60.55 25.78 270 top
C2210  10UF/6.3V  [TX_C0402_T02_H28]  49.38 90.55 0 top
C2211  10UF/6.3V  [TX_C0402_T02_H28]  52.34 48.74 180 top
C2212  10UF/6.3V  [TX_C0402_T02_H28]  57.56 51.74 0 top
C2213  10UF/6.3V  [TX_C0402_T02_H28]  49.45 54.43 180 top
C2214  10UF/6.3V  [TX_C0402_T02_H28]  49.48 52.35 180 top
C2215  10UF/6.3V  [TX_C0402_T02_H28]  57.3 69.01 180 top
C2216  10UF/6.3V  [TX_C0402_T02_H28]  57.33 67.97 180 top
C2217  10UF/6.3V  [TX_C0402_T02_H28]  57.46 63.81 90 top
C2218  10UF/6.3V  [TX_C0402_T02_H28]  57.16 85.62 180 top
C2219  10UF/6.3V  [TX_C0402_T02_H28]  52.86 44.71 180 top
C2220  1UF/6.3V  [TX_C0402]  62.48 25.78 270 top
C2221  1UF/6.3V  [TX_C0402]  61.54 25.78 270 top
C2222  1UF/6.3V  [TX_C0402]  46.19 25.11 270 top
C2223  1UF/6.3V  [TX_C0402]  45.27 25.11 270 top
C2224  1UF/6.3V  [TX_C0402]  70.08 74.65 180 top
C2225  1UF/6.3V  [TX_C0402]  65.96 60.84 180 top
C2226  1UF/6.3V  [TX_C0402]  70.33 58.83 180 top
C2227  1UF/6.3V  [TX_C0402]  61.24 87.73 0 top
C2228  1UF/6.3V  [TX_C0402]  62.92 38.25 0 top
C2229  1UF/6.3V  [TX_C0402]  70.28 85.28 180 top
C2230  1UF/6.3V  [TX_C0402]  69.91 39 180 top
C2231  1UF/6.3V  [TX_C0402]  65.96 59.76 180 top
C2232  10UF/6.3V  [TX_C0402_T02_H28]  56.54 25.75 270 top
C2233  10UF/6.3V  [TX_C0402_T02_H28]  57.58 25.75 270 top
C2234  1UF/6.3V  [TX_C0402]  57.91 62.36 0 top
C2235  1UF/6.3V  [TX_C0402]  57.56 50.75 0 top
C2236  1UF/6.3V  [TX_C0402]  58.01 53.16 270 top
C2237  1UF/6.3V  [TX_C0402]  57.45 75.28 180 top
C2238  1UF/6.3V  [TX_C0402]  52.04 42.12 180 top
C2239  1UF/6.3V  [TX_C0402]  50.36 79.37 225 top
C2240  1UF/6.3V  [TX_C0402]  59.74 30.38 180 top
C2241  1UF/6.3V  [TX_C0402]  57.31 42.6 180 top
C2242  1UF/6.3V  [TX_C0402]  69.22 24.26 270 top
C2243  1UF/6.3V  [TX_C0402]  70.13 24.26 270 top
C2300  0.1UF/16V  [TX_C0402]  33.2 47.02 90 top
C2301  0.1UF/16V  [TX_C0402]  39.47 47.14 90 top
C2302  0.1UF/16V  [TX_C0402]  46.13 30.18 0 top
C2303  0.1UF/16V  [TX_C0402]  35.46 25.81 270 top
C2304  0.1UF/16V  [TX_C0402]  44.76 37.85 90 top
C2305  0.1UF/16V  [TX_C0402]  24.08 38.97 180 top
C2306  0.1UF/16V  [TX_C0402]  32.23 47.02 90 top
C2307  0.1UF/16V  [TX_C0402]  27.36 26.72 270 top
C2308  0.1UF/16V  [TX_C0402]  46.76 41.31 270 top
C2309  0.1UF/16V  [TX_C0402]  24.16 33.51 180 top
C2310  1UF/6.3V  [TX_C0402]  34.49 46.13 90 top
C2311  2.2UF/6.3V  [TX_C0402]  46.1 47.6 90 top
C2312  10PF/50V  [TX_C0402]  43.74 43.36 0 top
C2313  0.1UF/16V  [TX_C0402]  47.55 31.57 270 top
C2314  0.1UF/16V  [TX_C0402]  44.98 34.37 90 top
C2315  0.1UF/16V  [TX_C0402]  40.97 25.73 270 top
C2316  10UF/6.3V  [TX_C0402_T02_H28]  25.95 45.02 0 top
C2317  2200PF/50V  [TX_C0402]  44.58 33.1 180 top
C2318  10PF/50V  [TX_C0402]  42.87 45.14 180 top
C2319  10PF/50V  [TX_C0402]  47.1 43.79 0 top
C2321  2200PF/50V  [TX_C0402]  45.11 36.58 0 top
C2400  4.7UF/6.3V  [TX_C0402_T02_H26]  26.24 23.32 180 top
C2401  0.01UF/16V  [TX_C0402]  31.27 47.02 90 top
C2500  0.1UF/16V  [TX_C0402]  93.12 24.4 90 top
C2501  4.7UF/6.3V  [TX_C0402_T02_H26]  91.24 24.4 90 top
C2502  10UF/6.3V  [TX_C0402_T02_H28]  97.63 13.06 180 top
C2503  0.1UF/16V  [TX_C0402]  94.11 24.4 90 top
C2504  0.1UF/16V  [TX_C0402]  92.2 24.4 90 top
C2505  0.1UF/16V  [TX_C0402]  93.19 29.62 180 top
C2506  4.7UF/6.3V  [TX_C0402_T02_H26]  97.63 14.1 180 top
C2600  0.1UF/16V  [TX_C0402]  15.55 73.05 90 top
C2601  10UF/6.3V  [TX_C0402_T02_H28]  16.59 73.05 90 top
C2900  0.1UF/16V  [TX_C0402]  21.95 62.87 0 bottom
C2901  0.1UF/16V  [TX_C0402]  22.02 67.52 0 bottom
C2902  0.1UF/16V  [TX_C0402]  21.97 60.41 0 bottom
C2903  0.1UF/16V  [TX_C0402]  21.97 59.49 0 bottom
C2904  0.1UF/16V  [TX_C0402]  21.16 65.23 0 bottom
C2905  0.1UF/16V  [TX_C0402]  22.02 66.6 0 bottom
C2906  0.1UF/16V  [TX_C0402]  21.95 61.95 0 bottom
C2907  0.1UF/16V  [TX_C0402]  21.16 64.31 0 bottom
C2908  10PF/50V  [TX_C0402]  25.04 67.44 90 top
C2909  10PF/50V  [TX_C0402]  27.76 63.15 0 top
C3000  4.7UF/6.3V  [TX_C0402_T02_H26]  50.67 98.35 270 bottom
C3001  0.1UF/25V  [TX_C0402]  60.85 98.34 270 bottom
C3002  0.1UF/25V  [TX_C0402]  59.87 97.84 270 bottom
C3003  1UF/6.3V  [TX_C0402]  56.74 100.07 180 top
C3004  0.1UF/16V  [TX_C0402]  69.88 99.03 90 bottom
C3005  0.1UF/16V  [TX_C0402]  68.91 99.03 90 bottom
C3006  0.1UF/16V  [TX_C0402]  67.97 97.72 90 bottom
C3007  0.1UF/16V  [TX_C0402]  67.05 97.72 90 bottom
C3008  0.1UF/16V  [TX_C0402]  65.1 98.67 90 bottom
C3009  0.1UF/16V  [TX_C0402]  66.02 98.67 90 bottom
C3010  1UF/6.3V  [TX_C0402]  44.09 98.99 180 bottom
C3011  0.1UF/16V  [TX_C0402]  62 98.22 270 bottom
C3100  10UF/6.3V  [TX_C0402_T02_H28]  224.36 19.26 0 top
C3101  0.1UF/16V  [TX_C0402]  224.36 22.15 0 top
C3102  0.1UF/16V  [TX_C0402]  224.36 20.27 0 top
C3103  10PF/50V  [TX_C0402]  224.36 21.21 0 top
C3104  0.22UF/16V  [TX_C0402]  212.17 18.82 0 bottom
C3105  0.22UF/16V  [TX_C0402]  212.01 17.91 0 bottom
C3106  0.22UF/16V  [TX_C0402]  213.61 17.5 0 bottom
C3107  0.22UF/16V  [TX_C0402]  213.56 16.59 0 bottom
C3108  10UF/6.3V  [TX_C0402_T02_H28]  224.33 16.26 0 top
C3109  0.1UF/16V  [TX_C0402]  224.36 18.24 0 top
C3110  0.1UF/16V  [TX_C0402]  224.33 17.25 0 top
C3111  0.22UF/16V  [TX_C0402]  214.43 14.58 0 top
C3112  0.22UF/16V  [TX_C0402]  214.43 15.5 0 top
C3113  0.22UF/16V  [TX_C0402]  216.36 9.13 0 top
C3114  0.22UF/16V  [TX_C0402]  216.36 8.21 0 top
C3115  10PF/50V  [TX_C0402]  221.79 6.73 0 top
C3116  10UF/6.3V  [TX_C0402_T02_H28]  224 2.49 0 top
C3117  0.1UF/16V  [TX_C0402]  224 1.5 0 top
C3118  0.1UF/16V  [TX_C0402]  224 3.48 0 top
C3119  10PF/50V  [TX_C0402]  224.1 4.42 0 top
C3120  10NF/25V  [TX_C0402]  121.67 14.15 180 bottom
C3121  10NF/25V  [TX_C0402]  121.66 13.24 180 bottom
C3122  10NF/25V  [TX_C0402]  121.67 12.3 180 bottom
C3123  10NF/25V  [TX_C0402]  121.67 11.38 180 bottom
C3124  10UF/25V  [TX_C0603_T02_H39]  110.19 16.26 90 bottom
C3125  0.1UF/16V  [TX_C0402]  111.76 17.07 0 bottom
C3127  10UF/25V  [TX_C0603_T02_H39]  108.86 16.26 90 bottom
C3600  0.1UF/16V  [TX_C0402]  208.86 85.6 0 bottom
C3601  1UF/16V  [TX_C0402]  208.86 86.57 0 bottom
C3602  0.1UF/16V  [TX_C0402]  205.51 62.89 0 bottom
C3603  0.1UF/16V  [TX_C0402]  208.86 88.57 180 bottom
C3604  0.1UF/16V  [TX_C0402]  142.06 18.82 0 bottom
C3605  1UF/6.3V  [TX_C0402]  102.46 83.9 0 top
C3700  0.1UF/16V  [TX_C0402]  126.34 89.44 270 bottom
C3701  0.1UF/16V  [TX_C0402]  11.07 55.86 0 top
C3702  33PF/50V  [TX_C0402]  151.1 18.85 270 top
C3703  33PF/50V  [TX_C0402]  150.72 22.94 180 top
C3704  0.1UF/16V  [TX_C0402]  154.51 23.9 180 top
C3705  10UF/6.3V  [TX_C0402_T02_H28]  154.51 24.89 180 top
C3706  2200PF/50V  [TX_C0402]  204.39 105.95 0 bottom
C3707  0.01UF/16V  [TX_C0402]  105.77 47.27 0 top
C3800  10UF/6.3V  [TX_C0402_T02_H28]  21.85 31.17 0 bottom
C3801  0.1UF/16V  [TX_C0402]  18.95 23.22 0 top
C3802  10UF/6.3V  [TX_C0402_T02_H28]  17.98 23.8 0 bottom
C3803  0.1UF/16V  [TX_C0402]  18.29 24.77 0 bottom
C3804  10UF/6.3V  [TX_C0402_T02_H28]  17.96 32.18 270 top
C3805  0.1UF/16V  [TX_C0402]  19.26 35.15 180 top
C3806  0.1UF/16V  [TX_C0402]  16.97 32.39 270 top
C3807  0.1UF/16V  [TX_C0402]  17.16 36.38 0 top
C3808  10UF/6.3V  [TX_C0805_T02_H55]  13.87 40.36 270 bottom
C3809  10UF/6.3V  [TX_C0805_T02_H55]  11.99 40.36 90 bottom
C3810  100PF/50V  [TX_C0402]  5.68 39.68 0 bottom
C3811  100PF/50V  [TX_C0402]  5.11 54 90 bottom
C3812  100PF/50V  [TX_C0402]  14.49 49.62 0 bottom
C3813  100PF/50V  [TX_C0402]  11.81 54.1 90 bottom
C3814  22PF/50V  [TX_C0402]  21.41 26.32 0 bottom
C3815  10UF/6.3V  [TX_C0402_T02_H28]  11.58 29.68 270 bottom
C3816  10PF/50V  [TX_C0402]  22.71 26.98 270 bottom
C3817  10UF/6.3V  [TX_C0402_T02_H28]  18.31 24.72 180 top
C3818  2.2UF/6.3V  [TX_C0603]  13.96 24.79 0 top
C3819  10UF/6.3V  [TX_C0402_T02_H28]  14.03 34.36 180 bottom
C3820  0.1UF/16V  [TX_C0402]  14.61 35.71 0 bottom
C3821  2.2UF/6.3V  [TX_C0603]  12.07 26.04 0 top
C3822  2.2UF/6.3V  [TX_C0402]  14.03 33.37 180 bottom
C3823  10UF/6.3V  [TX_C0402_T02_H28]  15.57 26.27 0 top
C3824  10UF/6.3V  [TX_C0402_T02_H28]  14.02 33.35 180 top
C3825  10UF/6.3V  [TX_C0402_T02_H28]  13.88 24.41 270 bottom
C3826  0.1UF/16V  [TX_C0402]  14.87 24.41 270 bottom
C3827  10UF/6.3V  [TX_C0402_T02_H28]  17.1 35.89 270 bottom
C3828  0.1UF/16V  [TX_C0402]  16.13 35.89 270 bottom
C3829  10UF/6.3V  [TX_C0402_T02_H28]  12.94 35.71 180 bottom
C3830  330PF/50V  [TX_C0402]  11.25 26.62 270 bottom
C3831  330PF/50V  [TX_C0402]  12.73 26.04 270 bottom
C3832  10UF/6.3V  [TX_C0402_T02_H28]  19.04 32.37 270 top
C3833  1UF/6.3V  [TX_C0402]  21.82 33.27 0 bottom
C3834  0.1UF/16V  [TX_C0402]  12.01 23.24 90 bottom
C3835  1000PF/25V  [TX_C0402]  4.6 19.84 270 top
C3836  1000PF/25V  [TX_C0402]  5.99 19.89 270 top
C3837  1000PF/25V  [TX_C0402]  7.35 19.86 270 top
C3838  1000PF/25V  [TX_C0402]  8.44 19.86 270 top
C3839  0.1UF/16V  [TX_C0402]  21.85 30.21 180 bottom
C3840  0.1UF/16V  [TX_C0402]  21.81 34.25 0 bottom
C3841  0.1UF/16V  [TX_C0402]  14.4 55.27 90 bottom
C3842  0.1UF/16V  [TX_C0402]  7.62 55.17 90 bottom
C3843  100PF/50V  [TX_C0402]  12.01 21.57 270 bottom
C3901  0.1UF/16V  [TX_C0402]  38.46 57.2 270 top
C3902  10UF/6.3V  [TX_C0402_T02_H28]  36.45 57.2 270 top
C3903  0.1UF/16V  [TX_C0402]  31.37 60.12 180 top
C3904  0.1UF/16V  [TX_C0402]  39.7 61.83 0 top
C3905  10UF/6.3V  [TX_C0402_T02_H28]  31.37 58.07 180 top
C3906  10UF/6.3V  [TX_C0402_T02_H28]  39.7 63.86 0 top
C3907  0.1UF/16V  [TX_C0402]  35.87 65.33 90 top
C3908  4.7UF/10V  [TX_C0402_T02_H26]  39.7 62.82 0 top
C3909  0.01UF/16V  [TX_C0402]  39.73 58.14 0 top
C3910  4.7UF/10V  [TX_C0402_T02_H26]  37.47 57.2 270 top
C3911  0.01UF/16V  [TX_C0402]  39.7 60.89 0 top
C3913  4.7UF/10V  [TX_C0402_T02_H26]  31.37 59.13 180 top
C3914  0.01UF/16V  [TX_C0402]  34.95 65.33 90 top
C5100  100PF/50V  [TX_C0402]  82.48 14.1 90 bottom
C5101  100PF/50V  [TX_C0402]  84.31 14.1 90 bottom
C5102  100PF/50V  [TX_C0402]  83.39 14.1 90 bottom
C5103  100PF/50V  [TX_C0402]  80.6 14 90 bottom
C5104  100PF/50V  [TX_C0402]  86.14 14.1 90 bottom
C5105  100PF/50V  [TX_C0402]  64.93 14.85 90 bottom
C5106  100PF/50V  [TX_C0402]  87.08 14.1 90 bottom
C5107  100PF/50V  [TX_C0402]  65.87 14.85 90 bottom
C5108  100PF/50V  [TX_C0402]  68.74 14.83 90 bottom
C5109  100PF/50V  [TX_C0402]  85.23 14.1 90 bottom
C5110  100PF/50V  [TX_C0402]  66.79 14.83 90 bottom
C5111  100PF/50V  [TX_C0402]  79.9 9.17 270 top
C5112  100PF/50V  [TX_C0402]  78.06 9.19 270 top
C5113  100PF/50V  [TX_C0402]  78.98 9.19 270 top
C5114  100PF/50V  [TX_C0402]  76.22 9.19 270 top
C5115  100PF/50V  [TX_C0402]  77.14 9.19 270 top
C5116  100PF/50V  [TX_C0402]  80.82 9.18 270 top
C5117  100PF/50V  [TX_C0402]  70.62 14.83 90 bottom
C5118  100PF/50V  [TX_C0402]  82.68 9.16 270 top
C5119  100PF/50V  [TX_C0402]  81.75 9.15 270 top
C5120  100PF/50V  [TX_C0402]  83.61 9.16 270 top
C5121  100PF/50V  [TX_C0402]  67.7 14.83 90 bottom
C5122  100PF/50V  [TX_C0402]  69.71 14.83 90 bottom
C5123  100PF/50V  [TX_C0402]  71.56 14.83 90 bottom
C5124  1UF/16V  [TX_C0402]  202.65 48.28 180 bottom
C5125  0.1UF/16V  [TX_C0402]  172.53 19.52 0 bottom
C5126  0.1UF/16V  [TX_C0402]  58.44 7.9 90 top
C5127  33PF/50V  [TX_C0402]  50.81 7.9 270 top
C5128  33PF/50V  [TX_C0402]  53.59 7.9 270 top
C5129  33PF/50V  [TX_C0402]  56.59 7.9 270 top
C5130  33PF/50V  [TX_C0402]  59.08 10.57 90 top
C5131  0.1UF/16V  [TX_C0402]  12.9 16.33 0 top
C5132  100PF/50V  [TX_C0402]  81.54 14 90 bottom
C5133  0.1UF/16V  [TX_C0402]  203.53 31.52 180 bottom
C5134  0.1UF/16V  [TX_C0402]  203.53 32.44 180 bottom
C5135  0.1UF/16V  [TX_C0402]  191.21 22.61 90 bottom
C5136  0.1UF/16V  [TX_C0402]  190.27 22.61 90 bottom
C5300  0.1UF/16V  [TX_C0402]  98.07 109.95 270 bottom
C5301  0.1UF/16V  [TX_C0402]  42.57 58.55 180 top
C5700  10NF/25V  [TX_C0402]  22.68 86.13 180 top
C5701  10NF/25V  [TX_C0402]  29.92 86.03 90 top
C5702  0.1UF/16V  [TX_C0402]  23.17 78.39 270 top
C5703  0.1UF/16V  [TX_C0402]  27.94 77.37 270 top
C5704  0.1UF/16V  [TX_C0402]  30.96 86.03 90 top
C5705  0.1UF/16V  [TX_C0402]  30.91 78.67 180 top
C5706  0.1UF/16V  [TX_C0402]  30.89 77.65 180 top
C5707  0.1UF/16V  [TX_C0402]  27 77.42 90 top
C5708  0.1UF/16V  [TX_C0402]  26.04 77.42 90 top
C5709  0.1UF/16V  [TX_C0402]  30.76 79.71 180 top
C5710  0.1UF/16V  [TX_C0402]  30.76 80.65 180 top
C5711  0.1UF/16V  [TX_C0402]  32.79 81.13 180 top
C5712  0.1UF/16V  [TX_C0402]  32.79 82.07 180 top
C5713  0.1UF/16V  [TX_C0402]  30.91 82.53 180 top
C5714  0.1UF/16V  [TX_C0402]  30.91 83.49 180 top
C5715  0.1UF/16V  [TX_C0402]  33.3 84.25 180 top
C5716  0.1UF/16V  [TX_C0402]  33.3 85.22 180 top
C5717  0.1UF/16V  [TX_C0402]  22.94 89.89 270 top
C5718  0.1UF/16V  [TX_C0402]  22 89.89 270 top
C5719  0.22UF/10V  [TX_C0402]  14.66 84.48 0 top
C5720  0.22UF/10V  [TX_C0402]  14.66 83.44 0 top
C5721  0.22UF/10V  [TX_C0402]  14.66 81.41 0 top
C5722  0.22UF/10V  [TX_C0402]  14.66 82.4 0 top
C5723  10UF/25V  [TX_C0603_T02_H39]  12.73 87.12 270 bottom
C5724  0.1UF/16V  [TX_C0402]  17.09 77.17 270 bottom
C5800  1UF/16V  [TX_C0402]  41.05 72.2 0 top
C5801  1UF/16V  [TX_C0402]  39.78 71.78 90 top
C5802  0.1UF/16V  [TX_C0402]  38.02 72.62 180 top
C5803  0.1UF/16V  [TX_C0402]  38.48 71.35 180 top
C5804  0.1UF/16V  [TX_C0402]  41.68 81.26 0 top
C5805  390PF/50V  [TX_C0402]  45.39 76.06 0 top
C5806  390PF/50V  [TX_C0402]  45.39 78.82 0 top
C5807  0.1UF/16V  [TX_C0402]  45.44 79.99 0 top
C5808  0.1UF/25V  [TX_C0402]  17.35 69.19 270 bottom
C5809  0.22UF/16V  [TX_C0402]  14 75.24 90 bottom
C5810  1UF/16V  [TX_C0402]  22.71 69.8 270 bottom
C5811  0.1UF/16V  [TX_C0402]  45.01 77.52 270 top
C5812  1UF/16V  [TX_C0402]  45.95 77.52 270 top
C5813  0.1UF/16V  [TX_C0402]  27.28 56.09 180 top
C5814  1UF/16V  [TX_C0402]  27.74 61.57 0 top
C5900  10UF/25V  [TX_C0603_T02_H39]  14.07 87.23 270 bottom
C5903  10UF/25V  [TX_C0603_T02_H39]  12.34 92.79 90 bottom
C5905  0.1UF/25V  [TX_C0402]  20.98 89.11 0 bottom
C5906  1000PF/25V  [TX_C0402]  18.87 88.78 270 top
C5907  22UF/6.3V  [TX_C0603_T02_H39]  18.42 94.52 90 bottom
C5908  22UF/6.3V  [TX_C0603_T02_H39]  21.13 94.52 90 bottom
C5909  22UF/6.3V  [TX_C0603_T02_H39]  22.48 91.85 270 bottom
C5910  22UF/6.3V  [TX_C0603_T02_H39]  19.76 94.52 90 bottom
C5911  22UF/6.3V  [TX_C0603_T02_H39]  21.11 91.85 270 bottom
C5912  100PF/50V  [TX_C0402]  17.91 88.78 270 top
C5913  22UF/6.3V  [TX_C0603_T02_H39]  22.48 94.52 90 bottom
C6000  0.22UF/10V  [TX_C0402]  139.17 83.85 225 top
C6001  0.22UF/10V  [TX_C0402]  139.83 83.19 225 top
C6002  0.22UF/10V  [TX_C0402]  141.15 81.87 225 top
C6003  0.22UF/10V  [TX_C0402]  140.49 82.52 225 top
C6004  0.22UF/10V  [TX_C0402]  138.5 84.51 225 top
C6005  0.22UF/10V  [TX_C0402]  137.85 85.17 225 top
C6006  0.22UF/10V  [TX_C0402]  136.96 85.88 225 top
C6007  0.22UF/10V  [TX_C0402]  136.3 86.53 225 top
C6008  0.22UF/10V  [TX_C0402]  154.33 103.79 90 bottom
C6009  0.22UF/10V  [TX_C0402]  155.27 103.79 90 bottom
C6010  0.22UF/10V  [TX_C0402]  156.24 103.79 90 bottom
C6011  0.22UF/10V  [TX_C0402]  157.2 103.79 90 bottom
C6012  0.22UF/10V  [TX_C0402]  158.14 103.79 90 bottom
C6013  0.22UF/10V  [TX_C0402]  159.08 103.79 90 bottom
C6014  0.22UF/10V  [TX_C0402]  160.02 103.79 90 bottom
C6015  0.22UF/10V  [TX_C0402]  160.96 103.79 90 bottom
C6016  0.1UF/16V  [TX_C0402]  140.06 87.38 90 bottom
C6200  0.1UF/16V  [TX_C0402]  147.31 91.63 270 bottom
C6201  0.1UF/16V  [TX_C0402]  155.11 91.99 180 top
C6202  0.1UF/16V  [TX_C0402]  152.73 89.28 180 top
C6203  0.1UF/16V  [TX_C0402]  152.65 92.38 180 top
C6300  120PF/50V  [TX_C0402_H20]  180.42 79.86 0 top
C6301  1UF/16V  [TX_C0402]  169.27 104.32 180 bottom
C6302  1UF/16V  [TX_C0402]  164.57 104.4 180 bottom
C6303  0.1UF/16V  [TX_C0402]  167.16 79.03 270 top
C6304  0.1UF/16V  [TX_C0402]  168.1 78.06 270 top
C6305  68PF/50V  [TX_C0402]  182.02 77.98 0 top
C6600  0.1UF/16V  [TX_C0402]  184.48 103.99 180 bottom
C6601  0.1UF/16V  [TX_C0402]  184.61 94.19 180 bottom
C6602  0.1UF/16V  [TX_C0402]  200.43 103.18 0 bottom
C6603  0.1UF/16V  [TX_C0402]  200.43 92.79 0 bottom
C6604  0.1UF/16V  [TX_C0402]  196.16 106.63 180 bottom
C6605  0.1UF/16V  [TX_C0402]  184.48 85.3 180 bottom
C6606  0.1UF/16V  [TX_C0402]  184.63 76.35 180 bottom
C6607  0.1UF/16V  [TX_C0402]  200.38 83.29 0 bottom
C6608  0.1UF/16V  [TX_C0402]  200.43 74.09 0 bottom
C6609  0.1UF/16V  [TX_C0402]  192.94 71.66 0 bottom
C6610  1UF/6.3V  [TX_C0402]  184.51 104.93 0 bottom
C6611  1UF/6.3V  [TX_C0402]  200.43 104.17 0 bottom
C6612  1UF/6.3V  [TX_C0402]  184.61 93.25 180 bottom
C6613  1UF/6.3V  [TX_C0402]  200.43 91.75 0 bottom
C6614  10UF/6.3V  [TX_C0402_T02_H28]  200.38 85.22 0 bottom
C6615  0.1UF/16V  [TX_C0402]  185.04 104.17 90 top
C6616  0.1UF/16V  [TX_C0402]  184.63 94.26 180 top
C6617  0.1UF/16V  [TX_C0402]  200.41 103.51 0 top
C6618  0.1UF/16V  [TX_C0402]  200.33 94.95 0 top
C6619  0.1UF/16V  [TX_C0402]  195.29 106.66 0 top
C6620  0.1UF/16V  [TX_C0402]  184.38 85.24 180 top
C6621  0.1UF/16V  [TX_C0402]  184.61 76.51 180 top
C6622  0.1UF/16V  [TX_C0402]  200.71 83.14 0 top
C6623  0.1UF/16V  [TX_C0402]  200.43 74.09 0 top
C6624  0.1UF/16V  [TX_C0402]  193.35 71.58 0 top
C6625  1UF/6.3V  [TX_C0402]  184.12 104.17 90 top
C6626  1UF/6.3V  [TX_C0402]  184.63 93.25 180 top
C6627  1UF/6.3V  [TX_C0402]  200.41 104.55 0 top
C6628  1UF/6.3V  [TX_C0402]  200.33 93.88 0 top
C6629  10UF/6.3V  [TX_C0402_T02_H28]  200.71 82.15 0 top
C6630  1UF/6.3V  [TX_C0402]  200.38 84.23 0 bottom
C6631  1UF/6.3V  [TX_C0402]  200.43 73.15 0 bottom
C6632  1UF/6.3V  [TX_C0402]  200.43 73.1 0 top
C6633  1UF/6.3V  [TX_C0402]  184.61 75.57 180 top
C6634  1UF/6.3V  [TX_C0402]  184.73 74.12 180 bottom
C6635  1UF/6.3V  [TX_C0402]  184.48 86.26 180 bottom
C6636  1UF/6.3V  [TX_C0402]  184.38 86.31 180 top
C6637  1UF/6.3V  [TX_C0402]  200.71 84.05 0 top
C6700  1UF/16V  [TX_C0402]  158.42 93.78 90 top
C6701  1UF/16V  [TX_C0402]  158.84 87.8 0 top
C6702  2.2UF/6.3V  [TX_C0402]  161.63 93.46 0 top
C6703  2.2UF/6.3V  [TX_C0402]  158.13 86.27 90 top
C6704  2.2UF/6.3V  [TX_C0402]  164.5 86.93 90 top
C6705  2.2UF/6.3V  [TX_C0402]  160.31 83.89 135 top
C6706  2.2UF/6.3V  [TX_C0402]  163.37 83.89 270 top
C6707  2.2UF/6.3V  [TX_C0402]  160 90.73 90 top
C6708  2.2UF/6.3V  [TX_C0402]  159.08 91.88 270 top
C6709  2.2UF/6.3V  [TX_C0402]  163.65 93.05 90 top
C6710  2.2UF/6.3V  [TX_C0402]  161.44 92.53 0 top
C6711  2.2UF/6.3V  [TX_C0402]  162.57 90.7 90 top
C6712  2.2UF/6.3V  [TX_C0402]  165.1 90.78 90 top
C6713  2.2UF/6.3V  [TX_C0402]  163.83 91.14 0 top
C6714  2.2UF/6.3V  [TX_C0402]  161.79 85.22 135 top
C6715  2.2UF/6.3V  [TX_C0402]  157.1 84.29 315 top
C6716  2.2UF/6.3V  [TX_C0402]  160.98 88.8 0 top
C6717  2.2UF/6.3V  [TX_C0402]  161.7 83.99 135 top
C6718  10UF/6.3V  [TX_C0402_T02_H28]  167.27 83.25 180 top
C6719  10UF/6.3V  [TX_C0402_T02_H28]  154.26 87.25 45 top
C6720  10UF/6.3V  [TX_C0402_T02_H28]  151.08 89.37 180 top
C6721  0.1UF/16V  [TX_C0402]  154.39 107.79 90 top
C6722  10UF/6.3V  [TX_C0402_T02_H28]  156.81 89.32 0 top
C6723  10UF/6.3V  [TX_C0402_T02_H28]  167.95 98.44 0 top
C6724  10UF/6.3V  [TX_C0402_T02_H28]  159.31 82.57 135 top
C6725  10UF/6.3V  [TX_C0402_T02_H28]  163.51 86.93 90 top
C6726  10UF/6.3V  [TX_C0402_T02_H28]  159.22 85.97 90 top
C6727  10UF/6.3V  [TX_C0402_T02_H28]  165.07 84.15 180 top
C6728  10UF/6.3V  [TX_C0402_T02_H28]  161.6 90.71 90 top
C6729  10UF/6.3V  [TX_C0402_T02_H28]  164.31 88.83 0 top
C6730  10UF/6.3V  [TX_C0402_T02_H28]  162.62 88.84 180 top
C6731  10UF/6.3V  [TX_C0402_T02_H28]  162.01 87.01 90 top
C6732  1UF/16V  [TX_C0402]  167.27 82.27 180 top
C6733  1UF/16V  [TX_C0402]  152.74 88.33 180 top
C6734  1UF/16V  [TX_C0402]  153.25 107.79 90 top
C6735  1UF/16V  [TX_C0402]  169.81 99.2 0 top
C6736  1UF/16V  [TX_C0402]  165.8 97.78 180 top
C6737  1UF/16V  [TX_C0402]  164.58 93.67 270 top
C6738  1UF/16V  [TX_C0402]  163.26 95.32 180 top
C6739  1UF/16V  [TX_C0402]  167.15 96.81 0 top
C6740  1UF/16V  [TX_C0402]  155.16 89.7 180 top
C6741  1UF/16V  [TX_C0402]  163.26 94.35 180 top
C6742  1UF/16V  [TX_C0402]  158.54 84.32 315 top
C6743  0.1UF/16V  [TX_C0402]  166.79 92.22 0 top
C6744  1UF/16V  [TX_C0402]  166.66 93.16 0 top
C6745  0.1UF/16V  [TX_C0402]  167.07 84.24 0 top
C6746  10UF/6.3V  [TX_C0402_T02_H28]  166.84 87.11 180 top
C6747  2.2UF/6.3V  [TX_C0402]  166.82 88.53 180 top
C6748  2.2UF/6.3V  [TX_C0402]  166.82 89.47 180 top
C6749  2.2UF/6.3V  [TX_C0402]  169.47 85.78 0 top
C6750  2.2UF/6.3V  [TX_C0402]  171.67 99.58 90 top
C6751  2.2UF/6.3V  [TX_C0402]  168.86 95.26 0 top
C6752  0.1UF/16V  [TX_C0402]  167.48 90.67 0 top
C6753  0.1UF/16V  [TX_C0402]  169.81 88.31 180 top
C6754  1UF/16V  [TX_C0402]  164.94 94.94 0 top
C6800  1UF/16V  [TX_C0402]  200.69 79.1 0 top
C6801  1UF/16V  [TX_C0402]  184.38 98.4 180 bottom
C6802  1UF/16V  [TX_C0402]  185.12 98.81 90 top
C6803  1UF/16V  [TX_C0402]  200.51 79.07 0 bottom
C6900  8.2PF/50V  [TX_C0402]  148.25 88.72 90 bottom
C6901  8.2PF/50V  [TX_C0402]  147.32 86.59 270 bottom
C6907  0.1UF/16V  [TX_C0402]  155.56 85.22 135 top
C6908  1UF/16V  [TX_C0402]  157.48 93.78 90 top
C7001  1UF/16V  [TX_C0402]  191.31 111.25 0 bottom
C7005  1UF/16V  [TX_C0402]  190.88 108.36 270 bottom
C7006  1UF/16V  [TX_C0402]  191.87 108.36 270 bottom
C7007  1000PF/50V  [TX_C0402]  185.14 110.31 180 bottom
C7008  1UF/16V  [TX_C0402]  185.14 109.37 180 bottom
C7100  10UF/6.3V  [TX_C0402_T02_H28]  155.16 88.71 180 top
C7101  10UF/6.3V  [TX_C0402_T02_H28]  163.26 96.84 180 top
C7102  1UF/16V  [TX_C0402]  155.16 90.69 180 top
C7103  1UF/16V  [TX_C0402]  165.8 95.87 180 top
CE2200  220UF/2V  [TX_C7343D_299X177]  45.11 88.29 90 top
CE2201  220UF/2V  [TX_C7343D_299X177]  48.86 63.03 270 top
CON2000  DDR4_SO_260P  [A_DDR4_260P_20_4H_REV_FOX]  66.18 58.95 90 bottom
CON2100  DDR4_SO_260P  [A_DDR4_260P_20_4HOLD_FOX]  53.43 59.95 270 bottom
CON2600  HDMI_CON_19P  [A_HDMI_19P_4H_RA_SMT_ACON]  3.68 66.4 90 bottom
CON3000  FPC_CON_30P  [TX_FPC_30P_20_2H_RA_ACES_B]  63.33 103.9 0 bottom
CON3100  NGFF_67P  [TX_NGFF_67P_20_4HOLD_ARG]  221.23 11.6 270 bottom
CON3101  FPC_CON_12P  [TX_FPC_12P_20_2H_RA_ACES_B]  114.43 11.2 180 bottom
CON3600  WTOB_CON_4P  [TX_WTOB_4P_39_2HD_RA_COLAY]  206.83 80 180 bottom
CON3601  WTOB_CON_10P  [TX_WTOB_10P_79_2HOLD_ACES]  136.03 10.5 180 bottom
CON3602  WTOB_CON_2P  [TX_WTOB_2P_49_2H_ACES_H138]  59.83 17.2 90 bottom
CON3800  WTOB_CON_6P  [WTOB_6P_39_2H_RA_CVI]  7.83 16.55 180 bottom
CON5100  FPC_CON_8P  [TX_FPC_8P_39_2HOLD_ACES_B]  54.23 7 180 bottom
CON5101  FPC_CON_4P  [TX_FPC_4P_39_2HOLD_RA_AC_B]  170.88 14.4 180 bottom
CON5102  FPC_CON_30P  [TX_FPC_30P_31_2HOLD_RA_ACE]  78.03 9 180 bottom
CON5103  WTOB_CON_50P  [A_WTOB_50P_20_4HD_IEX]  208.8 35.51 270 bottom
CON5104  WTOB_CON_20P  [TX_WTOB_20P_20_4HOLD]  195.07 17.33 180 bottom
